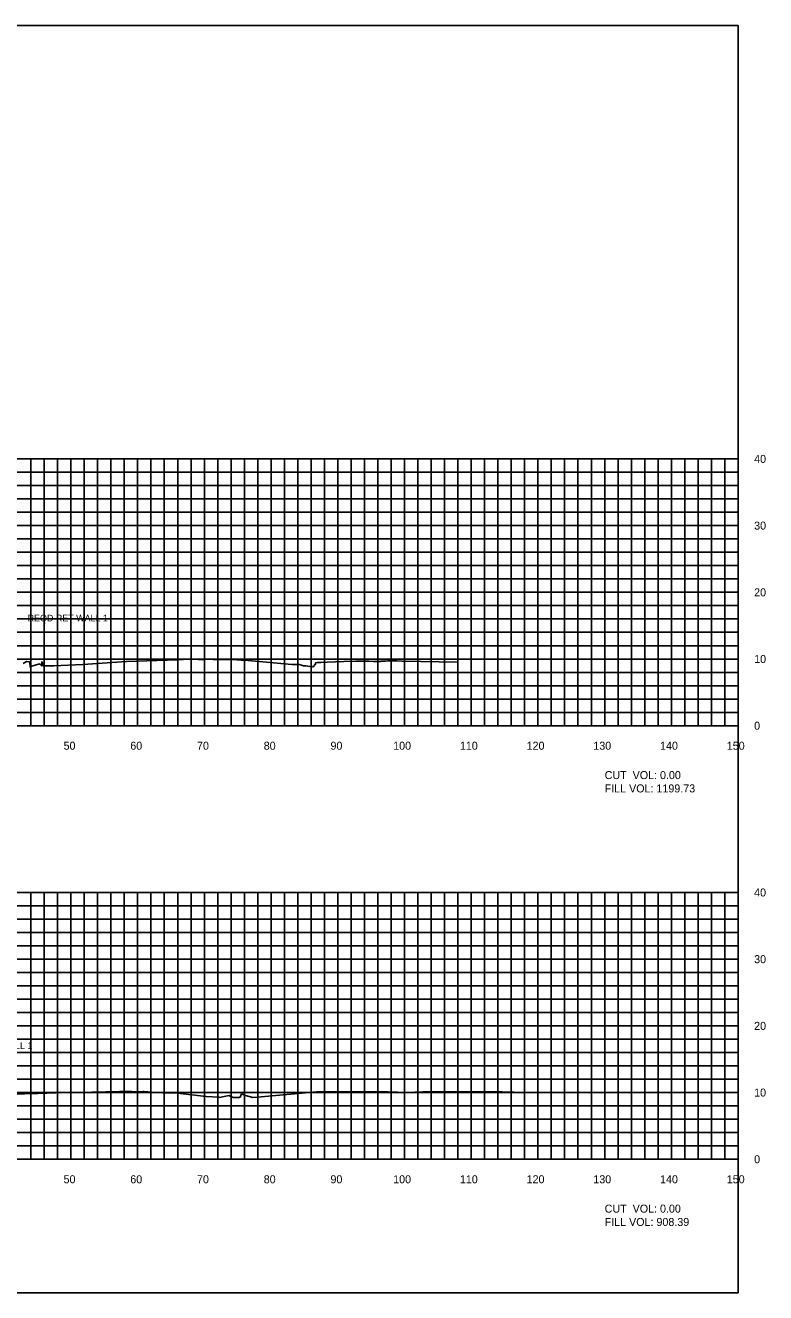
# Model space of a CAD drawing. Extents: x 1797652 to 1804145, y 245981 to 250269.
# Drawn here: x 1803014.2 to 1803125.1, y 250079.4 to 250269.4 of the extents above; entities that cross this region are included whole.
import ezdxf

# ---------------------------------------------------------------- set-up
doc = ezdxf.new("R2010")
doc.units = 0
for name, color, linetype in [('10', 7, 'Continuous'), ('3', 7, 'Continuous'), ('31', 7, 'Continuous'), ('60', 7, 'Continuous'), ('ANNO-TXT', 7, 'Continuous'), ('Level 62', 7, 'Continuous'), ('M-ROADS', 7, 'Continuous')]:
    doc.layers.add(name, color=color, linetype=linetype)

msp = doc.modelspace()

# ---------------------------------------------------------------- linework, layer by layer
msp.add_lwpolyline([(1802821, 250079.43), (1803121, 250079.43), (1803121, 250269.43), (1802821, 250269.43)], close=True)
at = {"layer": '60'}
for p, q in [((1803121, 250164.43), (1803121, 250204.43)), ((1803121.06, 250204.43), (1803121, 250204.43)), ((1803121.06, 250194.43), (1803121, 250194.43)), ((1803121.06, 250184.43), (1803121, 250184.43)), ((1803121.06, 250174.43), (1803121, 250174.43)), ((1802821, 250164.43), (1803121, 250164.43)), ((1803021, 250164.37), (1803021, 250164.43)), ((1803031, 250164.37), (1803031, 250164.43)), ((1803041, 250164.37), (1803041, 250164.43)), ((1803051, 250164.37), (1803051, 250164.43)), ((1803061, 250164.37), (1803061, 250164.43)), ((1803071, 250164.37), (1803071, 250164.43)), ((1803081, 250164.37), (1803081, 250164.43)), ((1803091, 250164.37), (1803091, 250164.43)), ((1803101, 250164.37), (1803101, 250164.43)), ((1803111, 250164.37), (1803111, 250164.43)), ((1803121, 250164.37), (1803121, 250164.43)), ((1803121.06, 250164.43), (1803121, 250164.43)), ((1803121, 250099.43), (1803121, 250139.43)), ((1803121.06, 250139.43), (1803121, 250139.43)), ((1803121.06, 250129.43), (1803121, 250129.43)), ((1803121.06, 250119.43), (1803121, 250119.43)), ((1803121.06, 250109.43), (1803121, 250109.43)), ((1802821, 250099.43), (1803121, 250099.43)), ((1803021, 250099.37), (1803021, 250099.43)), ((1803031, 250099.37), (1803031, 250099.43)), ((1803041, 250099.37), (1803041, 250099.43)), ((1803051, 250099.37), (1803051, 250099.43)), ((1803061, 250099.37), (1803061, 250099.43)), ((1803071, 250099.37), (1803071, 250099.43)), ((1803081, 250099.37), (1803081, 250099.43)), ((1803091, 250099.37), (1803091, 250099.43)), ((1803101, 250099.37), (1803101, 250099.43)), ((1803111, 250099.37), (1803111, 250099.43)), ((1803121, 250099.37), (1803121, 250099.43)), ((1803121.06, 250099.43), (1803121, 250099.43))]:
    msp.add_line(p, q, dxfattribs=at)
at = {"layer": 'Level 62'}
for p, q in [((1802821, 250204.43), (1803121, 250204.43)), ((1803015, 250164.43), (1803015, 250204.43)), ((1803017, 250164.43), (1803017, 250204.43)), ((1803019, 250164.43), (1803019, 250204.43)), ((1803021, 250164.43), (1803021, 250204.43)), ((1803023, 250164.43), (1803023, 250204.43)), ((1803025, 250164.43), (1803025, 250204.43)), ((1803027, 250164.43), (1803027, 250204.43)), ((1803029, 250164.43), (1803029, 250204.43)), ((1803031, 250164.43), (1803031, 250204.43)), ((1803033, 250164.43), (1803033, 250204.43)), ((1803035, 250164.43), (1803035, 250204.43)), ((1803037, 250164.43), (1803037, 250204.43)), ((1803039, 250164.43), (1803039, 250204.43)), ((1803041, 250164.43), (1803041, 250204.43)), ((1803043, 250164.43), (1803043, 250204.43)), ((1803045, 250164.43), (1803045, 250204.43)), ((1803047, 250164.43), (1803047, 250204.43)), ((1803049, 250164.43), (1803049, 250204.43)), ((1803051, 250164.43), (1803051, 250204.43)), ((1803053, 250164.43), (1803053, 250204.43)), ((1803055, 250164.43), (1803055, 250204.43)), ((1803057, 250164.43), (1803057, 250204.43)), ((1803059, 250164.43), (1803059, 250204.43)), ((1803061, 250164.43), (1803061, 250204.43)), ((1803063, 250164.43), (1803063, 250204.43)), ((1803065, 250164.43), (1803065, 250204.43)), ((1803067, 250164.43), (1803067, 250204.43)), ((1803069, 250164.43), (1803069, 250204.43)), ((1803071, 250164.43), (1803071, 250204.43)), ((1803073, 250164.43), (1803073, 250204.43)), ((1803075, 250164.43), (1803075, 250204.43)), ((1803077, 250164.43), (1803077, 250204.43)), ((1803079, 250164.43), (1803079, 250204.43)), ((1803081, 250164.43), (1803081, 250204.43)), ((1803083, 250164.43), (1803083, 250204.43)), ((1803085, 250164.43), (1803085, 250204.43)), ((1803087, 250164.43), (1803087, 250204.43)), ((1803089, 250164.43), (1803089, 250204.43)), ((1803091, 250164.43), (1803091, 250204.43)), ((1803093, 250164.43), (1803093, 250204.43)), ((1803095, 250164.43), (1803095, 250204.43)), ((1803097, 250164.43), (1803097, 250204.43)), ((1803099, 250164.43), (1803099, 250204.43)), ((1803101, 250164.43), (1803101, 250204.43)), ((1803103, 250164.43), (1803103, 250204.43)), ((1803105, 250164.43), (1803105, 250204.43)), ((1803107, 250164.43), (1803107, 250204.43)), ((1803109, 250164.43), (1803109, 250204.43)), ((1803111, 250164.43), (1803111, 250204.43)), ((1803113, 250164.43), (1803113, 250204.43)), ((1803115, 250164.43), (1803115, 250204.43)), ((1803117, 250164.43), (1803117, 250204.43)), ((1803119, 250164.43), (1803119, 250204.43)), ((1803121, 250164.43), (1803121, 250204.43)), ((1802821, 250202.43), (1803121, 250202.43)), ((1802821, 250200.43), (1803121, 250200.43)), ((1802821, 250198.43), (1803121, 250198.43)), ((1802821, 250196.43), (1803121, 250196.43)), ((1802821, 250194.43), (1803121, 250194.43)), ((1802821, 250192.43), (1803121, 250192.43)), ((1802821, 250190.43), (1803121, 250190.43)), ((1802821, 250188.43), (1803121, 250188.43)), ((1802821, 250186.43), (1803121, 250186.43)), ((1802821, 250184.43), (1803121, 250184.43)), ((1802821, 250182.43), (1803121, 250182.43)), ((1802821, 250180.43), (1803121, 250180.43)), ((1802821, 250178.43), (1803121, 250178.43)), ((1802821, 250176.43), (1803121, 250176.43)), ((1802821, 250174.43), (1803121, 250174.43)), ((1802821, 250172.43), (1803121, 250172.43)), ((1802821, 250170.43), (1803121, 250170.43)), ((1802821, 250168.43), (1803121, 250168.43)), ((1802821, 250166.43), (1803121, 250166.43)), ((1802821, 250164.43), (1803121, 250164.43)), ((1802821, 250139.43), (1803121, 250139.43)), ((1803015, 250099.43), (1803015, 250139.43)), ((1803017, 250099.43), (1803017, 250139.43)), ((1803019, 250099.43), (1803019, 250139.43)), ((1803021, 250099.43), (1803021, 250139.43)), ((1803023, 250099.43), (1803023, 250139.43)), ((1803025, 250099.43), (1803025, 250139.43)), ((1803027, 250099.43), (1803027, 250139.43)), ((1803029, 250099.43), (1803029, 250139.43)), ((1803031, 250099.43), (1803031, 250139.43)), ((1803033, 250099.43), (1803033, 250139.43)), ((1803035, 250099.43), (1803035, 250139.43)), ((1803037, 250099.43), (1803037, 250139.43)), ((1803039, 250099.43), (1803039, 250139.43)), ((1803041, 250099.43), (1803041, 250139.43)), ((1803043, 250099.43), (1803043, 250139.43)), ((1803045, 250099.43), (1803045, 250139.43)), ((1803047, 250099.43), (1803047, 250139.43)), ((1803049, 250099.43), (1803049, 250139.43)), ((1803051, 250099.43), (1803051, 250139.43)), ((1803053, 250099.43), (1803053, 250139.43)), ((1803055, 250099.43), (1803055, 250139.43)), ((1803057, 250099.43), (1803057, 250139.43)), ((1803059, 250099.43), (1803059, 250139.43)), ((1803061, 250099.43), (1803061, 250139.43)), ((1803063, 250099.43), (1803063, 250139.43)), ((1803065, 250099.43), (1803065, 250139.43)), ((1803067, 250099.43), (1803067, 250139.43)), ((1803069, 250099.43), (1803069, 250139.43)), ((1803071, 250099.43), (1803071, 250139.43)), ((1803073, 250099.43), (1803073, 250139.43)), ((1803075, 250099.43), (1803075, 250139.43)), ((1803077, 250099.43), (1803077, 250139.43)), ((1803079, 250099.43), (1803079, 250139.43)), ((1803081, 250099.43), (1803081, 250139.43)), ((1803083, 250099.43), (1803083, 250139.43)), ((1803085, 250099.43), (1803085, 250139.43)), ((1803087, 250099.43), (1803087, 250139.43)), ((1803089, 250099.43), (1803089, 250139.43)), ((1803091, 250099.43), (1803091, 250139.43)), ((1803093, 250099.43), (1803093, 250139.43)), ((1803095, 250099.43), (1803095, 250139.43)), ((1803097, 250099.43), (1803097, 250139.43)), ((1803099, 250099.43), (1803099, 250139.43)), ((1803101, 250099.43), (1803101, 250139.43)), ((1803103, 250099.43), (1803103, 250139.43)), ((1803105, 250099.43), (1803105, 250139.43)), ((1803107, 250099.43), (1803107, 250139.43)), ((1803109, 250099.43), (1803109, 250139.43)), ((1803111, 250099.43), (1803111, 250139.43)), ((1803113, 250099.43), (1803113, 250139.43)), ((1803115, 250099.43), (1803115, 250139.43)), ((1803117, 250099.43), (1803117, 250139.43)), ((1803119, 250099.43), (1803119, 250139.43)), ((1803121, 250099.43), (1803121, 250139.43)), ((1802821, 250137.43), (1803121, 250137.43)), ((1802821, 250135.43), (1803121, 250135.43)), ((1802821, 250133.43), (1803121, 250133.43)), ((1802821, 250131.43), (1803121, 250131.43)), ((1802821, 250129.43), (1803121, 250129.43)), ((1802821, 250127.43), (1803121, 250127.43)), ((1802821, 250125.43), (1803121, 250125.43)), ((1802821, 250123.43), (1803121, 250123.43)), ((1802821, 250121.43), (1803121, 250121.43)), ((1802821, 250119.43), (1803121, 250119.43)), ((1802821, 250117.43), (1803121, 250117.43)), ((1802821, 250115.43), (1803121, 250115.43)), ((1802821, 250113.43), (1803121, 250113.43)), ((1802821, 250111.43), (1803121, 250111.43)), ((1802821, 250109.43), (1803121, 250109.43)), ((1802821, 250107.43), (1803121, 250107.43)), ((1802821, 250105.43), (1803121, 250105.43)), ((1802821, 250103.43), (1803121, 250103.43)), ((1802821, 250101.43), (1803121, 250101.43)), ((1802821, 250099.43), (1803121, 250099.43))]:
    msp.add_line(p, q, dxfattribs=at)
at = {"layer": 'M-ROADS'}
for points in [[(1803013.82, 250173.74), (1803014.33, 250174.04), (1803014.79, 250174.01), (1803014.92, 250173.13), (1803015, 250173.32), (1803016.29, 250173.72), (1803016.3, 250173.72), (1803016.63, 250173.46), (1803016.63, 250173.38), (1803016.65, 250174.03), (1803016.88, 250173.4), (1803017.24, 250173.4), (1803017.84, 250173.39), (1803018.19, 250173.42), (1803018.43, 250173.43), (1803022.79, 250173.62), (1803029.34, 250174.05), (1803036.92, 250174.33), (1803037.87, 250174.36), (1803039.66, 250174.41), (1803040.11, 250174.37), (1803040.94, 250174.37), (1803041.14, 250174.41), (1803041.67, 250174.4), (1803042.3, 250174.37), (1803042.91, 250174.35), (1803042.97, 250174.34), (1803043.25, 250174.34), (1803043.34, 250174.34), (1803043.46, 250174.37), (1803044.9, 250174.37), (1803045.19, 250174.34), (1803046.52, 250174.25), (1803047.56, 250174.19), (1803054.1, 250173.63), (1803055.21, 250173.6), (1803055.56, 250173.52), (1803055.85, 250173.43), (1803056.21, 250173.4), (1803057.12, 250173.28), (1803057.23, 250173.29), (1803057.33, 250173.25), (1803057.67, 250173.67), (1803057.68, 250173.86), (1803057.93, 250173.93), (1803058.46, 250173.91), (1803059.43, 250173.95), (1803061.92, 250174.05), (1803063.68, 250174.09), (1803065.63, 250174.1), (1803066.36, 250174.08), (1803067.42, 250174.08), (1803067.52, 250174.1), (1803067.55, 250174.11), (1803067.57, 250174.09), (1803068.17, 250174.13), (1803068.5, 250174.14), (1803069.83, 250174.15), (1803070.64, 250174.13), (1803078.99, 250173.95)], [(1803010.75, 250109.09), (1803015.23, 250109.28), (1803016.03, 250109.28), (1803018.73, 250109.38), (1803021.74, 250109.43), (1803024.14, 250109.47), (1803028.27, 250109.6), (1803028.82, 250109.6), (1803028.88, 250109.6), (1803029.06, 250109.6), (1803029.3, 250109.6), (1803029.75, 250109.6), (1803030.14, 250109.59), (1803031.59, 250109.54), (1803031.78, 250109.61), (1803032, 250109.6), (1803033.06, 250109.51), (1803034.78, 250109.38), (1803036.97, 250109.33), (1803041.27, 250108.86), (1803043.2, 250108.73), (1803043.28, 250108.7), (1803043.95, 250108.83), (1803044.73, 250108.99), (1803044.74, 250109.01), (1803044.93, 250108.83), (1803045.37, 250108.71), (1803045.74, 250108.7), (1803045.77, 250108.7), (1803045.8, 250108.7), (1803045.94, 250108.71), (1803046, 250108.71), (1803046.12, 250108.7), (1803046.15, 250108.69), (1803046.2, 250108.69), (1803046.35, 250108.74), (1803046.58, 250109.22), (1803047.18, 250109), (1803048.26, 250108.7), (1803048.97, 250108.74), (1803057.83, 250109.53), (1803067.11, 250109.58), (1803071.38, 250109.46), (1803074.89, 250109.58), (1803085.63, 250109.52), (1803089.18, 250109.45), (1803097.25, 250109.47), (1803100.49, 250109.4)]]:
    msp.add_lwpolyline(points, dxfattribs=at)

# ---------------------------------------------------------------- texts
at = {"layer": '10'}
for s, p in [('50', (1803019.9, 250160.83)), ('60', (1803029.9, 250160.83)), ('70', (1803039.9, 250160.83)), ('80', (1803049.9, 250160.83)), ('90', (1803059.9, 250160.83)), ('100', (1803069.3, 250160.83)), ('110', (1803079.3, 250160.83)), ('120', (1803089.3, 250160.83)), ('130', (1803099.3, 250160.83)), ('140', (1803109.3, 250160.83)), ('150', (1803119.3, 250160.83)), ('50', (1803019.9, 250095.83)), ('60', (1803029.9, 250095.83)), ('70', (1803039.9, 250095.83)), ('80', (1803049.9, 250095.83)), ('90', (1803059.9, 250095.83)), ('100', (1803069.3, 250095.83)), ('110', (1803079.3, 250095.83)), ('120', (1803089.3, 250095.83)), ('130', (1803099.3, 250095.83)), ('140', (1803109.3, 250095.83)), ('150', (1803119.3, 250095.83))]:
    msp.add_text(s, height=1.2, dxfattribs=at).set_placement(p)
at = {"layer": '3'}
for p in [(1803014.51, 250180.07), (1803003.19, 250115.97)]:
    msp.add_text('REQD RET WALL 1', height=1, dxfattribs=at).set_placement(p)
at = {"layer": '31'}
for s, p in [('40', (1803123.4, 250203.83)), ('30', (1803123.4, 250193.83)), ('20', (1803123.4, 250183.83)), ('10', (1803123.4, 250173.83)), ('0', (1803123.4, 250163.83)), ('40', (1803123.4, 250138.83)), ('30', (1803123.4, 250128.83)), ('20', (1803123.4, 250118.83)), ('10', (1803123.4, 250108.83)), ('0', (1803123.4, 250098.83))]:
    msp.add_text(s, height=1.2, dxfattribs=at).set_placement(p)
at = {"layer": 'ANNO-TXT'}
for s, p in [('CUT  VOL: 0.00', (1803101, 250156.43)), ('FILL VOL: 1199.73', (1803101, 250154.43)), ('CUT  VOL: 0.00', (1803101, 250091.43)), ('FILL VOL: 908.39', (1803101, 250089.43))]:
    msp.add_text(s, height=1.2, dxfattribs=at).set_placement(p)

doc.saveas('drawing.dxf')
